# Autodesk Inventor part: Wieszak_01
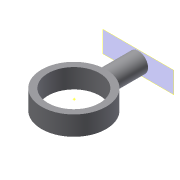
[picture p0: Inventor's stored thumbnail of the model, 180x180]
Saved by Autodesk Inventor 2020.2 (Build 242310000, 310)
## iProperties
Created: 2014-09
Part Number: Wieszak_01
Material: Ogólny
Document SubType Name: Modeling
Designer: F.Stasiak
Density: 1 g/cm^3
Appearance: Domyślna
Catalog Web Link: www.expertbooks.pl
Manager: www.cadconsulting.pl
Company: Fabian Stasiak CAD Consulting
Author: F.Stasiak
Subject: Zbiór ćwiczeń. Autodesk Inventor 2020. Kurs Professional
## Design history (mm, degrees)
sketch "Szkic1"
  geometry: C1 r 5 at (0, 0); C2 r 4 at (0, 0); 1 further point
  constraints: 2 centre point, 2 coincident
  dimensions: "d0" = 10 diameter of C1; "d1" = 8 diameter of C2
extrude "Wyciągnięcie proste1" new body sketch "Szkic1" stored distance "d2" = 3; taper "d3" = 0 deg
node "Płaszczyzna konstrukcyjna1"
sketch "Szkic2"
  geometry: C1 r 1.5 at (0, 0); 1 further point
  constraints: 1 centre point, 1 coincident
  dimensions: "d5" = 3 diameter of C1
extrude "Wyciągnięcie proste2" join sketch "Szkic2" stored distance "d6" = 3; taper "d7" = 0 deg
node "Bryła1"
